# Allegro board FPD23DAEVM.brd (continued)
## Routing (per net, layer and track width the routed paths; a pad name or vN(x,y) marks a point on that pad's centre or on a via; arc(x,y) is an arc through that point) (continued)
N15696379: length 65.4
  TOP w0.178: v1(43.18,33.66) 43.18,22.48 56.52,9.14 56.52,6.35 J2.32
  BOTTOM w0.178: v1(43.18,33.66) 43.18,39.6 52.96,49.38 RN2.16
N15736550: length 54.2
  TOP w0.178: v1(27.3,38.23) 27.56,38.23 27.81,38.48 29.72,38.48 33.17,41.94 33.17,49.55 34.94,51.32 RN5.6 ; U4.27 21.35,39.47 21.72,39.1 v1(21.72,38.73)
  BOTTOM w0.178: v1(27.3,38.23) 26.8,38.73 v1(21.72,38.73)
N15737945: length 45.8
  TOP w0.178: RN5.5 34.94,51.82 32.82,49.7 32.82,43.18 32.82,42.08 29.7,38.97 U4.29
N15738621: length 45.8
  TOP w0.178: U4.30 29.7,39.47 32.46,42.23 32.46,43.33 32.46,43.33 32.46,49.84 34.94,52.32 RN5.4
N15739305: length 45.6
  TOP w0.178: RN5.3 63.49,52.82 63.34,52.96 35.08,52.96 32.11,49.99 32.11,43.47 32.11,42.59 29.98,40.47 U4.32
N15741654: length 45.5
  TOP w0.178: RN5.2 34.93,53.32 31.75,50.14 31.75,43.62 31.75,42.74 29.98,40.97 U4.33
N15742354: length 44.8
  TOP w0.178: U4.34 v1(29.41,41.47) ; v1(33.53,41.27) 33.53,49.4 34.95,50.82 RN5.7
  BOTTOM w0.178: v1(29.41,41.47) 32.96,41.47 33.16,41.27 v1(33.53,41.27)
N15743062: length 45.4
  TOP w0.178: U4.35 30.48,41.97 31.39,42.89 31.39,43.77 31.39,50.29 35.08,53.98 63.33,53.98 63.49,53.82 RN5.1
N15744198: length 45.1
  TOP w0.178: v1(18.92,40) 19.34,40 19.38,39.97 U4.26 ; RN8.4 34.43,37.35 32.51,35.43 21.97,35.43 21.08,36.32 v1(20.57,36.32)
  BOTTOM w0.178: v1(20.57,36.32) 20.57,39.37 19.94,40.01 19.29,40.01 v1(18.92,40)
N15747608: length 49
  TOP w0.178: v1(24.26,51.82) 23.87,51.43 22.04,51.43 22.01,51.47 21.6,51.47 21.57,51.44 21.37,51.44 21.33,51.47 U4.3 ; v1(31.11,38.73) 33.27,38.73 33.39,38.85 RN8.1
  BOTTOM w0.178: v1(24.26,51.82) 24.64,51.82 25.65,50.8 25.65,46.54 26.22,45.97 26.54,45.97 26.7,45.82 27.07,45.82 28.91,43.98 28.91,38.79 28.96,38.73 v1(31.11,38.73)
N15748336: length 49.2
  TOP w0.178: RN8.2 33.78,38.35 33.02,37.59 v1(31.11,37.59) ; v1(24.26,50.93) 22.86,50.93 22.4,50.47 U4.5
  BOTTOM w0.178: v1(31.11,37.59) 29.6,37.59 28.55,38.64 28.55,43.84 26.92,45.47 26.04,45.47 25.3,46.2 25.3,49.32 25.27,49.34 25.27,50.29 24.64,50.93 v1(24.26,50.93)
N15750252: length 49.4
  TOP w0.178: v1(31.11,36.45) 32.77,36.45 34.17,37.85 RN8.3 ; U4.6 22.92,49.97 v1(23.24,50.29)
  BOTTOM w0.178: v1(31.11,36.45) 30.24,36.45 28.19,38.49 28.19,43.69 26.77,45.11 25.89,45.11 25.68,45.32 24.94,46.06 24.94,49.17 24.89,49.22 24.89,49.78 24.38,50.29 v1(23.24,50.29)
N15750996: length 5.5
  TOP w0.305: U4.2 18.52,51.97 17.14,53.34 R26.2
N15751370: length 49.1
  TOP w0.178: v1(39.12,45.34) 43.69,45.34 44.73,44.3 RN7.1 ; v1(22.48,52.45) 21.35,52.45 21.33,52.47 U4.1
  BOTTOM w0.178: v1(39.12,45.34) 39.12,48.77 35.31,52.58 22.97,52.58 22.85,52.45 v1(22.48,52.45)
N15751746: length 41.6
  TOP w0.178: U4.55 29.09,51.97 29.1,51.96 v1(29.46,51.96) ; RN7.2 44.34,43.79 44.07,44.07 40.64,44.07 40.39,44.32 v1(39.12,44.32)
  BOTTOM w0.178: v1(29.46,51.96) 29.83,51.96 29.84,51.97 35.28,51.97 38.62,48.63 38.62,44.82 v1(39.12,44.32)
N15752124: length 41.9
  TOP w0.178: RN7.3 40.14,43.3 40.13,43.31 v1(39.12,43.31) ; v1(30.73,51.44) 30.37,51.44 30.34,51.46 29.68,51.46 29.67,51.47 29.24,51.47 29.24,51.47 U4.54
  BOTTOM w0.178: v1(39.12,43.31) 38.27,44.16 38.27,48.35 35.14,51.47 31.14,51.47 31.1,51.44 v1(30.73,51.44)
N15752504: length 42.2
  TOP w0.178: U4.53 v1(29.46,50.97) ; RN7.4 43.3,42.79 43.18,42.67 38.73,42.67 v1(38.1,43.31)
  BOTTOM w0.178: v1(38.1,43.31) 38.1,43.68 37.91,43.87 37.91,48.07 35.05,50.93 29.88,50.93 29.83,50.97 v1(29.46,50.97)
N15752886: length 42.4
  TOP w0.178: v1(38.1,42.29) 43.43,42.29 43.44,42.3 RN7.5 ; v1(30.73,50.29) 29.34,50.29 29.01,49.97 U4.51
  BOTTOM w0.178: v1(38.1,42.29) 37.84,42.55 37.84,42.64 37.55,42.93 37.55,47.79 35.05,50.29 v1(30.73,50.29)
N15754502: length 44.5
  TOP w0.178: v1(35.81,41.02) 39.48,41.02 39.76,41.3 RN7.7 ; U4.50 29.04,49.47 29.1,49.53 v1(29.46,49.53)
  BOTTOM w0.178: v1(29.46,49.53) 30.25,48.74 34.95,48.74 36.84,46.85 36.84,42.05 v1(35.81,41.02)
N15759288: length 46.4
  TOP w0.178: v1(35.81,40.01) 41.53,40.01 42.32,40.79 RN7.8 ; U4.49 30.43,48.97 v1(30.73,49.28)
  BOTTOM w0.178: v1(35.81,40.01) 37.2,41.39 37.2,46.99 35.09,49.1 33.71,49.1 33.53,49.28 v1(30.73,49.28)
N15761170: length 42.3
  TOP w0.178: v1(29.46,48.39) 29.05,47.97 U4.47 ; RN7.6 36.42,41.79 36.18,42.04 v1(35.81,42.04)
  BOTTOM w0.178: v1(35.81,42.04) 36.45,42.67 36.45,46.35 34.42,48.39 v1(29.46,48.39)
N15764711: length 37.1
  TOP w0.178: RN6.1 36.04,49.38 v1(34.16,47.5) ; v1(30.73,47.88) 29.65,47.88 29.24,47.47 U4.46
  BOTTOM w0.178: v1(34.16,47.5) 33.79,47.5 33.77,47.47 31.14,47.47 v1(30.73,47.88)
N15767513: length 37.1
  TOP w0.178: v1(34.16,46.61) 36.43,48.87 RN6.2 ; U4.45 29.08,46.97 29.1,46.99 v1(29.46,46.99)
  BOTTOM w0.178: v1(29.46,46.99) 31.75,46.99 32.13,46.61 v1(34.16,46.61)
N15768326: length 37.5
  TOP w0.178: v1(34.16,45.72) 36.82,48.38 RN6.3 ; v1(30.73,46.35) 29.72,46.35 29.34,45.97 29.1,45.97 29.09,45.97 U4.43
  BOTTOM w0.178: v1(30.73,46.35) 31.11,45.97 31.5,45.97 31.75,45.72 v1(34.16,45.72)
N15769147: length 39.1
  TOP w0.178: v1(29.46,42.8) 29.1,42.8 28.92,42.97 U4.37 ; v1(34.16,42.04) 35.18,43.05 35.18,44.32 37.73,46.87 RN6.6
  BOTTOM w0.178: v1(34.16,42.04) 30.99,42.04 30.23,42.8 v1(29.46,42.8)
N15769559: length 38.8
  TOP w0.178: v1(30.73,43.43) 30.37,43.43 30.33,43.47 U4.38 ; v1(34.16,42.93) 34.8,43.56 34.8,44.7 37.47,47.38 RN6.5
  BOTTOM w0.178: v1(30.73,43.43) 31.62,43.43 32.13,42.93 v1(34.16,42.93)
N15769973: length 38.3
  TOP w0.178: U4.39 28.98,43.97 29.08,44.07 v1(29.46,44.07) ; v1(34.16,43.94) 34.16,44.83 37.21,47.87 RN6.4
  BOTTOM w0.178: v1(34.16,43.94) 31.88,43.94 31.75,44.07 v1(29.46,44.07)
N15799422: length 10.5
  TOP w0.152: v1(67.69,29.21) U5.6 ; R23.2 v1(63.25,33.66)
  BOTTOM w0.152: v1(63.25,33.66) 66.04,33.66 67.69,32 v1(67.69,29.21)
N15814147: length 8.5
  TOP w0.152: R32.1 58.43,34.43 58.93,34.92 62.74,34.92 64.01,33.66 R33.2
N15821065: length 2.5
  TOP w0.152: R22.2 U5.8
N15926102: length 3.7
  TOP w0.152: R36.1 16.95,17.13 16.84,17.02 JP6.3
N148619201: length 2.5
  TOP w0.152: U5.5 R21.2
N148620200: length 2.5
  TOP w0.152: R20.2 U5.4

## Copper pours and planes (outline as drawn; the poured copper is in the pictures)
3.3V on LYR_3: 0.64,74.3 1.35,76.12 3.17,76.83 111.12,76.83 112.93,76.1 113.67,74.3 113.67,3.17 112.91,1.39 111.12,0.64 15.88,0.64 15.88,10.54 26.04,20.7 26.04,26.67 26.8,27.43 107.82,27.43 109.09,28.7 109.09,39.12 106.81,41.4 102.74,41.4 101.35,40.01 101.35,35.69 99.95,34.29 82.93,34.29 81.66,35.56 81.66,56.26 88.01,62.61 88.01,68.71 86.11,70.61 69.09,70.61 67.56,69.09 67.56,56.39 59.69,48.51 44.2,48.51 40.77,51.94 40.77,60.07 38.23,62.61 35.31,62.61 33.02,60.33 33.02,55.24 32.38,54.61 27.3,54.61 25.4,52.7 25.4,43.81 26.04,43.18 26.04,36.32 25.15,35.43 23.88,35.43 23.11,36.2 21.46,36.2 20.45,35.18 20.45,33.53 25.4,28.57 25.4,20.95 15.37,10.92 15.37,0.64 3.3,0.64 1.61,1.18 0.64,2.67
+5V on LYR_3: 40.13,59.56 38.1,61.59 35.56,61.59 33.66,59.69 33.66,28.57 34.29,27.94 107.31,27.94 108.46,29.08 108.46,38.73 106.55,40.64 103,40.64 101.98,39.62 101.98,35.31 100.33,33.66 82.55,33.66 81.03,35.18 81.03,56.9 87.25,63.12 87.25,68.2 85.6,69.85 69.47,69.85 68.45,68.83 68.45,56.13 60.2,47.88 44.07,47.88 40.13,51.82
VCC on LYR_3: 20.95,33.66 20.95,35.05 21.46,35.56 22.99,35.56 23.75,34.8 25.15,34.8 26.42,36.07 26.42,43.43 25.91,43.94 25.91,52.58 27.43,54.1 32.26,54.1 33.02,53.34 33.02,28.7 32.38,28.07 26.54,28.07
VSS on LYR_2: 0.64,74.3 1.35,76.12 3.17,76.83 111.12,76.83 112.93,76.1 113.67,74.3 113.67,3.17 112.91,1.39 111.12,0.64 3.3,0.64 1.61,1.18 0.64,2.67
N14862082 on TOP: 61.59,21.46 61.59,24.89 60.96,25.53 60.96,26.92 61.21,27.18 62.23,27.18 62.61,27.56 62.61,30.99 62.99,31.37 64.14,31.37 64.64,30.86 67.18,30.86 67.18,30.1 67.06,29.97 64.77,29.97 64.64,29.84 64.64,27.43 66.8,25.27 66.8,21.08 66.29,20.57 62.48,20.57
N14862082 on BOTTOM: 64.52,30.99 64.52,29.72 64.26,29.46 62.74,29.46 62.61,29.34 62.61,26.67 64.01,25.27 66.17,25.27 66.8,24.64 66.8,21.08 66.29,20.57 62.48,20.57 61.59,21.46 61.59,26.04 60.96,26.67 60.96,27.18 61.09,27.3 61.09,30.86 61.59,31.37 64.14,31.37
N15439034 on TOP, BOTTOM: 54.74,64.52 54.74,75.44 54.1,76.07 42.42,76.07 41.91,75.56 41.91,64.52 44.45,61.98 46.35,61.98 46.86,61.47 46.86,57.53 47.24,57.15 49.15,57.15 49.53,57.53 49.53,61.47 50.04,61.98 52.2,61.98
N15439034 on LYR_3: 54.74,64.52 54.74,75.44 54.1,76.07 42.42,76.07 41.91,75.56 41.91,64.52 45.09,61.34 45.09,58.29 46.23,57.15 49.15,57.15 49.53,57.53 49.53,61.47 50.04,61.98 52.2,61.98

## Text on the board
BOTTOM: LAYER 4 (SECONDARY SIDE)
Board Geometry/Soldermask Bottom: SOLDERMASK (SECONDARY SIDE)
Ref Des/Silkscreen Bottom: 0+ | 2+ | VSS | CLK | 1+ | 3+ | 2- | 0- | 1- | 3- | REF | PCLK | R0 | R1 | R2 | R3 | R4 | R5 | R6 | R7 | G0 | G1 | G2 | G3 | G4 | G5 | G6 | G7 | B0 | B1 | B2 | B3 | B4 | B5 | B6 | B7 | HS | VS | DE | SILKSCREEN (SECONDARY SIDE)
User.Comments: HDMI ADAPTER BOARD (05-15-13) | DESIGNED BY: SVTRONICS
TOP: LAYER 1 (PRIMARY SIDE)
Board Geometry/Soldermask Top: SOLDERMASK (PRIMARY SIDE)
Ref Des/Silkscreen Top: 3+ | 1+ | VSS | CLK | 2+ | 0+ | HIGH | PDN | LOW | REF | VDD | 12V_MAX | A0 | A1 | A2 | 20 | 19 | BSEL/SCL | 1 | 2 | 3.3V | SUPPLY | CTL3 | CTL2 | CTL1 | EDGE/ | SCL | GTPLG | SDA | ISEL/RST | BSEL/SDA | DSEL/SDA | DDC_D | BSE/SCL | DDC_C | DKEN | PD | J3 | 1- | 3- | 0- | 2- | J2 | SV600969 - | FPD-Link II/III Display Adapter | REV A | PTC | EDGE/HPD | R0 | R1 | R2 | R3 | GND | R4 | R5 | R6 | R7 | G0 | 12V | G1 | G2 | G3 | G4 | G5 | G6 | G7 | B0 | B1 | B2 | B3 | B4 | B5 | MSEN/PO1 | B6 | B7 | HS | VS | DE | PCLK | Texas Instruments | - | SILKSCREEN (PRIMARY SIDE)
LYR_2: LAYER 2
LYR_3: LAYER 3
DIMENSION: LAYER 2 - BOTTOM SIDE (SOLDER) | LAYER 1 - TOP SIDE (COMPONENT) | LAYER 2 - GND | LAYER 3 - POWER | LAYER STACKUP | (FINISHED PLATING UP TO 1.0 oz) | COPPER WEIGHT | 2.  APPLY 4000 BN SOLDERMASK OVER BARE COPPER ( SMOBC ) | 3.  SOLDERMASK ARTWORK HAS ZERO [0] OVERSIZED PADS. | FAB NOTES: | 1.  HOLE CHART IS IN MILS. | 2.  THE PWB SHALL BE FABRICATED TO IPC-6012, | 4.  BOARD MATERIAL & CONSTRUCTION TO BE U.L. | 5.  MINIMUM COPPER WALL THICKNESS OF PLATED-THRU | 3.  BOARD MATERIAL SHALL BE FR-4 OR | 6.  OVERALL BOARD THICKNESS TO BE .062 +/- 10% | 7.  MAX WARP & TWIST TO BE .0075 INCHES PER INCH. | 8.  BOARD MUST BE ELECTRICALLY TESTED USING SUPPLIED | PROCESS NOTES: | 1.  PLATE ALL EXPOSED AREAS WITH ELECTROLESS | 4.  VIAS SHALL BE EXPOSED OR COVERED BY SOLDERMASK PER ARTWORK. | 5.  SILKSCREEN BOTH SIDES USING LPI SILKSCREEN OR EQUIVALENT. | 7.  100 OHM DIFFERENTIAL CONTROLLED IMPEDANCE ON TRACEE OF .005" (J3-U4) AND U1-U7-J4) | 8.  50 OHM SINGLE ENDED CONTROLLED IMPEDANCE ON TRACEE OF .007" (U4- RNs--U5-J3-J2) | 6.  BOARD TO BE PANALIZED WITH .500" RAIL ON EDGES. | EQUIVALENT, ROHS COMPLIANT AND LEAD FREE ASSEMBLY CAPABLE. | CLASS 2 AND WORKMANSHIP SHALL CONFORM TO | IPC-A-600, CLASS 2.  CURRENT REVISIONS. | BOARD MATERIAL SHALL MEET OR EXCEED IPC-4101B. COLOR: NATURAL | APPROVED AND MARKED ON THE FINISHED BOARD. | HOLES TO BE .001 INCH, WITH A MINIMUM | ANNULAR RING OF .002 INCH. | AND APPLIES AFTER ALL LAMINATION AND PLATING | PROCESSES, MEASURED FROM COPPER TO COPPER. | IPC-D-356 NETLIST. | IMMERSION SILVER. | COLOR: GREEN, SOLDERMASK SHALL | CONFORM TO IPC-SM-840, CLASS H.  CURRENT REV. | FABRICATION VENDOR IS ALLOWED TO ADJUST THE COMPONENT SOLDERMASK | PADS TO MEET THEIR TOOLING REQUIREMENTS WHILE MAINTAINING WEBBING | BETWEEN ADJACENT PADS. | 3 MIL (76um) ELECTROLESS SOLDERMASK STENCIL. | COLOR: WHITE. | +/- 10% | .062 | FABRICATION DRAWING
DISPLAY_TOP: SOLDERPASTE (PRIMARY SIDE)
SOLDERPASTE_BOT: SOLDERPASTE (SECONDARY SIDE)
User.13: FIGURE | SIZE | 12.0 | 38.0 | 51.0 | 94.0 | 156.0 | 118.0x39.0 | 138.0x39.0 | DRILL CHART: TOP to BOTTOM | ALL UNITS ARE IN MILS | TOLERANCE | +0.0/-0.0 | +3.0/-3.0 | PLATED | QTY | 280 | 136 | 4 | 1
